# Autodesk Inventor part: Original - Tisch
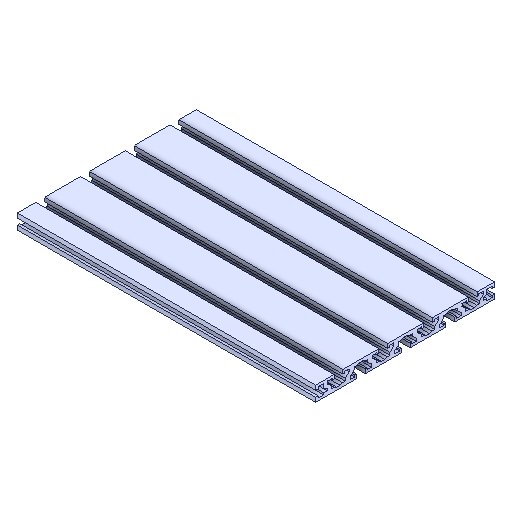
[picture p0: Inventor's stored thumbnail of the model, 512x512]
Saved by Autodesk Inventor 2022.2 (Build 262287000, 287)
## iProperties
Created: 2024-09
Part Number: Original - Tisch
Material: Generico
Document SubType Name: Modeling
Designer: 18907419
Density: 1 g/cm^3
Appearance: Default
Author: 18907419
Revision Number: ANY
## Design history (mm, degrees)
feature "Schnitt-Linear austragen5"
node "Solido1"
